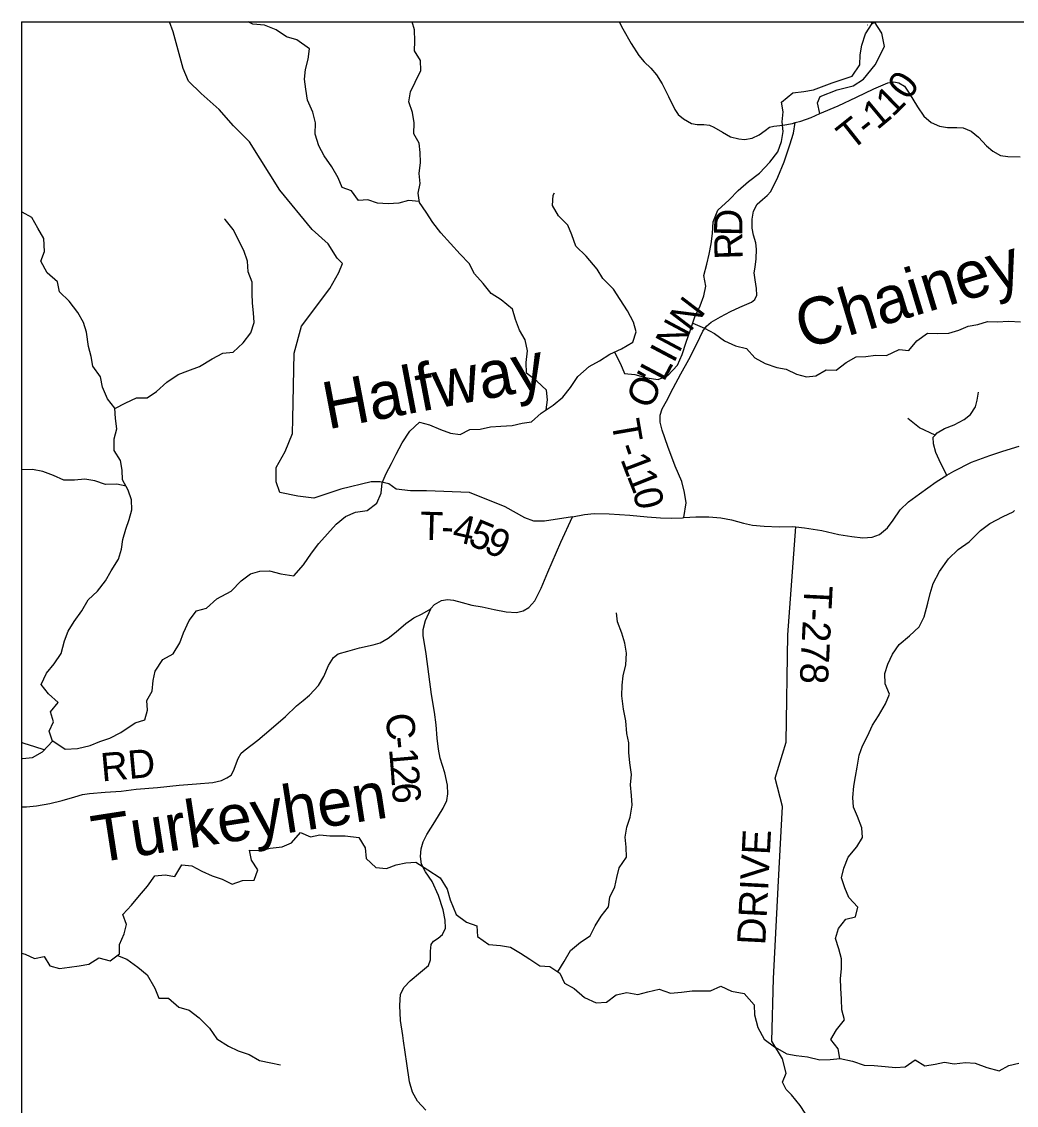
# Model space of a CAD drawing. Extents: x -84548 to 2262448, y -162180 to 525962.
# Drawn here: x 31945 to 42517, y 159360 to 170872 of the extents above; entities that cross this region are included whole.
import ezdxf

# ---------------------------------------------------------------- set-up
doc = ezdxf.new("R2010")
doc.units = 0
for name, color, linetype in [('GM_X_County', 7, 'Continuous'), ('GM_X_County_Road', 7, 'Continuous'), ('GM_X_Minor_Lake', 7, 'Continuous'), ('GM_X_Minor_River_Text', 7, 'Continuous'), ('GM_X_State_Route', 7, 'Continuous'), ('GM_X_Township_Road', 7, 'Continuous'), ('GM_X_Township_ROW', 7, 'Continuous'), ('GM_X_Unincorporated_Text', 7, 'Continuous')]:
    doc.layers.add(name, color=color, linetype=linetype)

msp = doc.modelspace()

# ---------------------------------------------------------------- linework, layer by layer
at = {"layer": 'GM_X_County'}
for q in [(31945, 134968), (67849, 170872)]:
    msp.add_line((31945, 170872), q, dxfattribs=at)
at = {"layer": 'GM_X_Minor_Lake'}
for points in [[(37799, 165611), (37503, 165565), (37389, 165565), (37294, 165603), (37085, 165717), (36704, 165869), (36248, 165888), (36077, 165888), (35925, 165907), (35849, 165964), (35754, 165983), (35659, 165983), (35336, 165907), (35051, 165812), (34880, 165831), (34689, 165869), (34651, 165983), (34651, 166136), (34746, 166307), (34823, 166497), (34826, 166653), (34842, 167352), (34918, 167637), (35222, 168037), (35317, 168208), (35355, 168303), (35298, 168360), (35203, 168512), (35032, 168664), (34690, 169082), (34367, 169595), (34196, 169767), (34044, 169938), (33853, 170109), (33720, 170242), (33663, 170375), (33557, 170766), (33516, 170872)], [(38296, 170872), (38336, 170798), (38423, 170641), (38505, 170514), (38561, 170445), (38634, 170379), (38691, 170308), (38751, 170211), (38820, 170078), (38889, 169941), (38924, 169888), (38981, 169841), (39066, 169792), (39124, 169780), (39196, 169779), (39256, 169774), (39302, 169751), (39393, 169699), (39480, 169650), (39567, 169628), (39629, 169621), (39711, 169635), (39782, 169671), (39847, 169718), (39894, 169751), (39940, 169762), (40034, 169774), (40137, 169792), (40167, 169800), (40225, 169816), (40336, 169856), (40427, 169896), (40623, 169978), (40817, 170070), (41003, 170158), (41150, 170221), (41214, 170232), (41268, 170223), (41327, 170188), (41378, 170113), (41465, 169969), (41533, 169870), (41610, 169801), (41701, 169763), (41787, 169749), (41885, 169749), (41953, 169744), (42038, 169710), (42115, 169647), (42201, 169553), (42268, 169496), (42349, 169449), (42427, 169439), (42557, 169436)], [(40427, 169896), (40403, 170009), (40431, 170079), (40613, 170149), (40781, 170191), (40892, 170261), (41018, 170414), (41116, 170610), (41088, 170750), (41008, 170872)], [(38983, 165604), (39008, 165759), (38991, 165870), (38961, 165986), (38890, 166151), (38812, 166358), (38754, 166531), (38730, 166617), (38731, 166693), (38751, 166761), (38798, 166840), (38869, 166978), (38952, 167132), (39035, 167282), (39121, 167450), (39186, 167583), (39225, 167638), (39274, 167681), (39371, 167735), (39478, 167793), (39579, 167841), (39702, 167894), (39739, 167921), (39758, 167967), (39755, 168039), (39741, 168129), (39730, 168203), (39740, 168263), (39751, 168354), (39755, 168456), (39747, 168524), (39723, 168606), (39710, 168679), (39710, 168776), (39724, 168858), (39763, 168933), (39818, 168984), (39869, 169025), (39906, 169068), (39981, 169222), (40048, 169383), (40110, 169563), (40147, 169688), (40167, 169800)], [(40024, 162405), (40031, 162533), (39955, 162837), (40069, 163217), (40088, 164358), (40172, 165505)], [(31945, 162532), (31995, 162531), (32104, 162543), (32246, 162568), (32375, 162599), (32512, 162636), (32592, 162661), (32665, 162671), (32833, 162686), (33003, 162698), (33162, 162717), (33388, 162735), (33621, 162760), (33805, 162774), (33976, 162791), (34070, 162811), (34127, 162838), (34173, 162869), (34198, 162912), (34247, 163045), (34280, 163100), (34321, 163137), (34455, 163240), (34597, 163359), (34750, 163492), (34865, 163604), (34938, 163662), (35005, 163717), (35099, 163821), (35157, 163915), (35205, 164034), (35261, 164117), (35310, 164156), (35413, 164186), (35535, 164219), (35680, 164252), (35757, 164275), (35842, 164323), (35925, 164391), (36027, 164479), (36114, 164539), (36203, 164583), (36293, 164633)], [(39986, 161676), (40024, 162403), (40024, 162405)], [(40363, 157412), (40411, 157457), (40487, 157628), (40506, 158807), (40392, 159092), (40221, 159358), (40126, 159472), (40069, 159529), (40031, 159605), (40069, 159700), (40031, 159852), (39917, 160042), (39936, 160708), (39986, 161675), (39986, 161676)]]:
    msp.add_lwpolyline(points, dxfattribs=at)
at = {"layer": 'GM_X_Minor_River_Text'}
for points in [[(35996, 160100), (35996, 160100), (35970, 160260), (35963, 160422), (35972, 160541), (36010, 160615), (36075, 160683), (36185, 160774), (36268, 160846), (36290, 160905), (36292, 160999), (36297, 161067), (36321, 161103), (36371, 161137), (36417, 161176), (36450, 161242), (36446, 161326), (36425, 161436), (36376, 161590), (36310, 161736), (36237, 161840), (36195, 161922), (36184, 162002), (36192, 162084), (36212, 162158), (36253, 162237), (36338, 162373), (36424, 162516), (36463, 162600), (36475, 162668), (36470, 162761), (36442, 162893), (36393, 163049), (36376, 163145), (36362, 163261), (36351, 163403), (36332, 163535), (36301, 163723), (36272, 163940), (36243, 164158), (36214, 164352), (36214, 164414), (36239, 164509), (36293, 164633), (36295, 164637), (36332, 164679), (36408, 164724), (36472, 164734), (36534, 164726), (36628, 164703), (36730, 164675), (36838, 164655), (36966, 164628), (37096, 164603), (37204, 164597), (37274, 164615), (37334, 164650), (37398, 164718), (37465, 164853), (37538, 165023), (37676, 165342), (37799, 165611), (37927, 165636), (38031, 165647), (38188, 165643), (38410, 165630), (38594, 165613), (38736, 165600), (38852, 165598), (38970, 165603), (38983, 165604), (39110, 165613), (39250, 165612), (39376, 165600), (39490, 165579), (39618, 165545), (39712, 165522), (39836, 165514), (39998, 165507), (40138, 165508), (40172, 165505), (40266, 165496), (40448, 165465), (40632, 165426), (40768, 165402), (40884, 165389), (40986, 165395), (41064, 165424), (41147, 165494), (41209, 165578), (41284, 165687), (41370, 165771), (41487, 165858), (41665, 165983), (41780, 166054), (41852, 166098), (42041, 166191), (42237, 166264), (42375, 166311), (42546, 166364)], [(36242, 159308), (36152, 159403), (36100, 159501), (36069, 159611), (36040, 159804), (36005, 160044), (35996, 160100)]]:
    msp.add_lwpolyline(points, dxfattribs=at)
at = {"layer": 'GM_X_State_Route'}
msp.add_line((40984, 170853), (40967, 170872), dxfattribs=at)
for points in [[(36171, 168962), (36056, 168974), (35953, 168946), (35841, 168936), (35728, 168946), (35626, 168978), (35525, 168972), (35451, 169076), (35350, 169112), (35310, 169212), (35242, 169329), (35159, 169447), (35105, 169555), (35065, 169679), (35069, 169796), (35041, 169910), (34983, 170038), (34967, 170157), (34951, 170261), (34963, 170365), (34991, 170475), (35003, 170584), (34870, 170678), (34760, 170710), (34651, 170786), (34528, 170836), (34402, 170846), (34352, 170872)], [(37521, 166750), (37533, 166855), (37525, 166957), (37421, 167053), (37310, 167137), (37306, 167252), (37322, 167374), (37296, 167492), (37238, 167595), (37194, 167707), (37162, 167819), (37043, 167917), (36936, 167985), (36852, 168090), (36757, 168194), (36703, 168302), (36605, 168404), (36502, 168515), (36400, 168629), (36315, 168739), (36245, 168847), (36173, 168950), (36161, 169050), (36181, 169154), (36169, 169258), (36185, 169377), (36181, 169481), (36169, 169581), (36114, 169681), (36116, 169798), (36098, 169906), (36062, 170020), (36078, 170126), (36129, 170231), (36189, 170355), (36183, 170459), (36119, 170561), (36123, 170664), (36119, 170786), (36095, 170872)], [(38245, 167363), (38309, 167238), (38352, 167135), (38464, 167123), (38589, 167087), (38711, 167071), (38814, 167113), (38916, 167224), (38967, 167338), (39009, 167468), (39053, 167600), (39101, 167735), (39156, 167855), (39196, 167959), (39218, 168062), (39196, 168176), (39226, 168296), (39252, 168402), (39272, 168511), (39286, 168623), (39296, 168745), (39345, 168871), (39465, 168978), (39562, 169080), (39670, 169176), (39787, 169262), (39896, 169379), (39982, 169491), (40022, 169601), (40038, 169705), (40028, 169808), (40040, 169914), (40020, 170018), (40141, 170118), (40258, 170132), (40360, 170148), (40561, 170221), (40666, 170259), (40772, 170293), (40855, 170413), (40857, 170519), (40875, 170622), (40913, 170744), (40985, 170852), (41012, 170872)], [(40933, 170840), (40935, 170840)], [(38442, 167468), (38476, 167578), (38448, 167679), (38384, 167799), (38305, 167921), (38235, 168030), (38122, 168144), (38062, 168244), (37944, 168380), (37835, 168489), (37791, 168607), (37751, 168711), (37650, 168811), (37586, 168920), (37594, 169028), (37610, 169054)], [(32273, 163227), (32238, 163335), (32284, 163435), (32252, 163539), (32335, 163641), (32230, 163730), (32154, 163832), (32208, 163950), (32290, 164050), (32365, 164159), (32401, 164295), (32439, 164397), (32503, 164501), (32586, 164614), (32652, 164730), (32753, 164822), (32837, 164932), (32896, 165039), (32974, 165161), (33006, 165269), (33022, 165371), (33054, 165482), (33089, 165582), (33115, 165686), (33113, 165794), (33079, 165897), (33018, 166005), (33014, 166107), (32996, 166211), (32930, 166318), (32928, 166440), (32956, 166546), (32942, 166658), (32936, 166767), (32859, 166867), (32805, 166989), (32783, 167099), (32701, 167212), (32683, 167316), (32654, 167420), (32634, 167574), (32602, 167677), (32544, 167783), (32451, 167903), (32349, 168003), (32325, 168110), (32218, 168204), (32150, 168328), (32188, 168430), (32182, 168569), (32116, 168677), (32054, 168791), (31951, 168847), (31945, 168842)], [(32936, 166762), (33052, 166823), (33167, 166875), (33278, 166877), (33378, 166943), (33487, 167043), (33607, 167123), (33712, 167162), (33834, 167208), (33971, 167290), (34084, 167350), (34194, 167360), (34301, 167462), (34381, 167566), (34415, 167677), (34409, 167779), (34399, 167883), (34395, 167983), (34395, 168104), (34353, 168216), (34347, 168328), (34305, 168443), (34194, 168663), (34108, 168771), (34100, 168779)], [(39078, 167670), (39202, 167615), (39310, 167560), (39417, 167480), (39532, 167430), (39650, 167400), (39739, 167300), (39847, 167242), (39972, 167200), (40072, 167181), (40179, 167127), (40285, 167099), (40386, 167109), (40496, 167175), (40601, 167169), (40708, 167252), (40814, 167310), (40917, 167314), (41021, 167328), (41136, 167326), (41272, 167390), (41373, 167380), (41461, 167480), (41574, 167562), (41682, 167560), (41799, 167562), (41906, 167596), (42006, 167636), (42107, 167657), (42211, 167687), (42312, 167683), (42438, 167689), (42561, 167685)], [(31945, 163035), (31953, 163046), (32059, 163054), (32168, 163116), (32278, 163232), (32409, 163142), (32538, 163150), (32674, 163182), (32777, 163226), (32881, 163262), (33000, 163321), (33151, 163423), (33253, 163457), (33283, 163557), (33275, 163659), (33332, 163760), (33342, 163872), (33366, 163974), (33444, 164096), (33555, 164155), (33627, 164273), (33667, 164379), (33724, 164509), (33804, 164614), (33909, 164640), (34021, 164742), (34172, 164822), (34277, 164932), (34377, 165005), (34478, 165033), (34578, 165039), (34699, 165005), (34839, 164986), (34940, 165101), (35026, 165227), (35105, 165327), (35197, 165433), (35288, 165534), (35388, 165614), (35493, 165660), (35619, 165680), (35720, 165756), (35766, 165864), (35776, 165973), (35819, 166073), (35877, 166177), (35925, 166279), (35989, 166398), (36070, 166522), (36172, 166616), (36281, 166588), (36398, 166538), (36504, 166500), (36607, 166488), (36707, 166540), (36820, 166542), (36930, 166568), (37037, 166576), (37157, 166582), (37264, 166608), (37364, 166622), (37467, 166714), (37594, 166799), (37698, 166883), (37779, 166987), (37857, 167103), (37978, 167208), (38088, 167268), (38195, 167340), (38321, 167398), (38442, 167468)], [(33057, 165936), (32956, 165959), (32835, 165955), (32723, 165993), (32616, 166013), (32508, 166001), (32393, 166003), (32282, 166051), (32172, 166095), (32061, 166115), (31947, 166113), (31945, 166113)], [(40641, 159858), (40623, 159959), (40544, 160059), (40605, 160163), (40689, 160269), (40663, 160375), (40659, 160488), (40653, 160604), (40649, 160706), (40659, 160811), (40659, 160917), (40629, 161021), (40595, 161131), (40627, 161238), (40705, 161338), (40806, 161362), (40834, 161464), (40735, 161566), (40695, 161669), (40657, 161775), (40683, 161879), (40729, 161995), (40822, 162106), (40882, 162206), (40874, 162308), (40828, 162428), (40786, 162529), (40780, 162631), (40790, 162751), (40806, 162853), (40826, 162954), (40848, 163080), (40882, 163180), (40934, 163280), (40987, 163399), (41051, 163499), (41125, 163625), (41168, 163727), (41123, 163836), (41119, 163946), (41152, 164048), (41202, 164152), (41270, 164257), (41381, 164349), (41483, 164443), (41538, 164551), (41578, 164694), (41602, 164796), (41632, 164902), (41700, 165032), (41797, 165165), (41899, 165265), (42014, 165347), (42135, 165465), (42235, 165540), (42378, 165614), (42482, 165666), (42498, 165678)], [(37643, 160779), (37710, 160889), (37778, 161003), (37885, 161093), (37989, 161159), (38040, 161268), (38104, 161370), (38182, 161470), (38197, 161570), (38249, 161681), (38271, 161781), (38297, 161883), (38375, 161995), (38371, 162104), (38359, 162210), (38377, 162316), (38414, 162422), (38434, 162547), (38426, 162653), (38416, 162765), (38428, 162873), (38410, 162998), (38400, 163108), (38398, 163210), (38379, 163310), (38365, 163445), (38343, 163569), (38323, 163711), (38327, 163822), (38339, 163922), (38365, 164038), (38375, 164162), (38357, 164271), (38325, 164375), (38277, 164495), (38269, 164591)], [(32186, 163135), (32085, 163170), (31971, 163204), (31945, 163215)], [(31945, 160975), (31981, 160965), (32081, 160921), (32186, 160941), (32244, 160841), (32347, 160813), (32453, 160829), (32556, 160841), (32658, 160859), (32765, 160927), (32885, 160895), (32986, 160969), (32984, 161069), (33036, 161180), (33060, 161280), (33022, 161386), (33111, 161488), (33199, 161589), (33283, 161689), (33360, 161799), (33472, 161809), (33575, 161791), (33647, 161915), (33754, 161903), (33862, 161849), (33969, 161797), (34075, 161761), (34182, 161709), (34293, 161747), (34417, 161753), (34457, 161861), (34387, 161963), (34367, 162072), (34488, 162066), (34588, 162092), (34713, 162106), (34815, 162150), (34910, 162258), (35014, 162214), (35115, 162232), (35219, 162224), (35384, 162222), (35529, 162206), (35595, 162094), (35607, 161981), (35708, 161887), (35822, 161875), (35927, 161915), (36027, 161935), (36134, 161943), (36263, 161861), (36393, 161777), (36468, 161657), (36500, 161542), (36564, 161386), (36673, 161304), (36783, 161268), (36791, 161154), (36912, 161069), (37033, 161059), (37141, 161039), (37246, 160975), (37348, 160913), (37453, 160843), (37559, 160833), (37666, 160765), (37716, 160658), (37817, 160600), (37929, 160506), (38050, 160450), (38160, 160456), (38265, 160534), (38379, 160560), (38494, 160538), (38601, 160564), (38721, 160594), (38840, 160550), (38958, 160562), (39073, 160576), (39266, 160576), (39377, 160626), (39489, 160572), (39624, 160548), (39730, 160428), (39734, 160321), (39769, 160185), (39837, 160061), (39947, 159981), (40076, 159906), (40177, 159888), (40297, 159874), (40428, 159844), (40538, 159848), (40645, 159858), (40774, 159830), (40898, 159788), (41005, 159782), (41123, 159774), (41232, 159762), (41334, 159768)], [(32964, 160953), (33064, 160913), (33179, 160829), (33279, 160745), (33362, 160604), (33404, 160498), (33507, 160500), (33617, 160402), (33726, 160372), (33832, 160290), (33943, 160181), (34021, 160065), (34142, 159989), (34248, 159939), (34365, 159899), (34472, 159837), (34592, 159812), (34695, 159790)], [(41334, 159768), (41443, 159844), (41546, 159778), (41654, 159796), (41755, 159820), (41857, 159802), (41976, 159814), (42080, 159808), (42203, 159760), (42334, 159728), (42436, 159784), (42545, 159808)]]:
    msp.add_lwpolyline(points, dxfattribs=at)
at = {"layer": 'GM_X_Township_ROW'}
for points in [[(41780, 166054), (41716, 166179), (41661, 166294), (41636, 166386), (41632, 166460), (41653, 166480), (41677, 166503), (41752, 166551), (41857, 166591), (41964, 166645), (42029, 166700), (42083, 166780), (42100, 166850), (42114, 166937)], [(41653, 166480), (41486, 166559), (41364, 166657)]]:
    msp.add_lwpolyline(points, dxfattribs=at)

# ---------------------------------------------------------------- texts
at = {"layer": 'GM_X_County_Road'}
for s, rotation, p in [('C', 276.324, (35810, 163512)), ('-', 275.6057, (35837, 163268)), ('1', 274.9395, (35849, 163146)), ('2', 274.3339, (35865, 162963)), ('6', 274.0155, (35879, 162779))]:
    msp.add_text(s, height=300, rotation=rotation, dxfattribs=at).set_placement(p)
at = {"layer": 'GM_X_Township_Road'}
for s, rotation, p in [('0', 54.6454, (41371, 170025)), ('1', 44.2443, (41200, 169851)), ('1', 39.7739, (41039, 169716)), ('T', 38.5484, (40762, 169494)), ('-', 38.7842, (40939, 169635)), ('D', 88.9217, (39603, 168592)), ('R', 91.741, (39611, 168349)), ('N', 52.56, (39050, 167566)), ('N', 61.9384, (38932, 167344)), ('I', 62.1017, (38875, 167235)), ("'", 62.2001, (38739, 166979)), ('L', 62.1047, (38770, 167037)), ('O', 65.2215, (38630, 166743)), ('T', 279.7801, (38211, 166623)), ('-', 289.1641, (38263, 166350)), ('1', 290.8135, (38306, 166225)), ('1', 291.6543, (38374, 166048)), ('0', 282.8093, (38438, 165888)), ('T', 358.4077, (36176, 165368)), ('4', 347.255, (36509, 165358)), ('5', 337.4086, (36676, 165321)), ('-', 357.2982, (36399, 165362)), ('9', 333.5979, (36842, 165253)), ('T-278', 267.1941, (40266, 164890)), ('RD', 5.2796, (32799, 162800)), ('DRIVE', 87.0767, (39848, 161058))]:
    msp.add_text(s, height=300, rotation=rotation, dxfattribs=at).set_placement(p)
at = {"layer": 'GM_X_Unincorporated_Text'}
for s, rotation, p in [('Chainey', 16.809, (40259, 167389)), ('Halfway', 10.8087, (35198, 166540)), ('Turkeyhen', 8.8092, (32733, 161935))]:
    msp.add_text(s, height=500, rotation=rotation, dxfattribs=at).set_placement(p)

doc.saveas('drawing.dxf')
